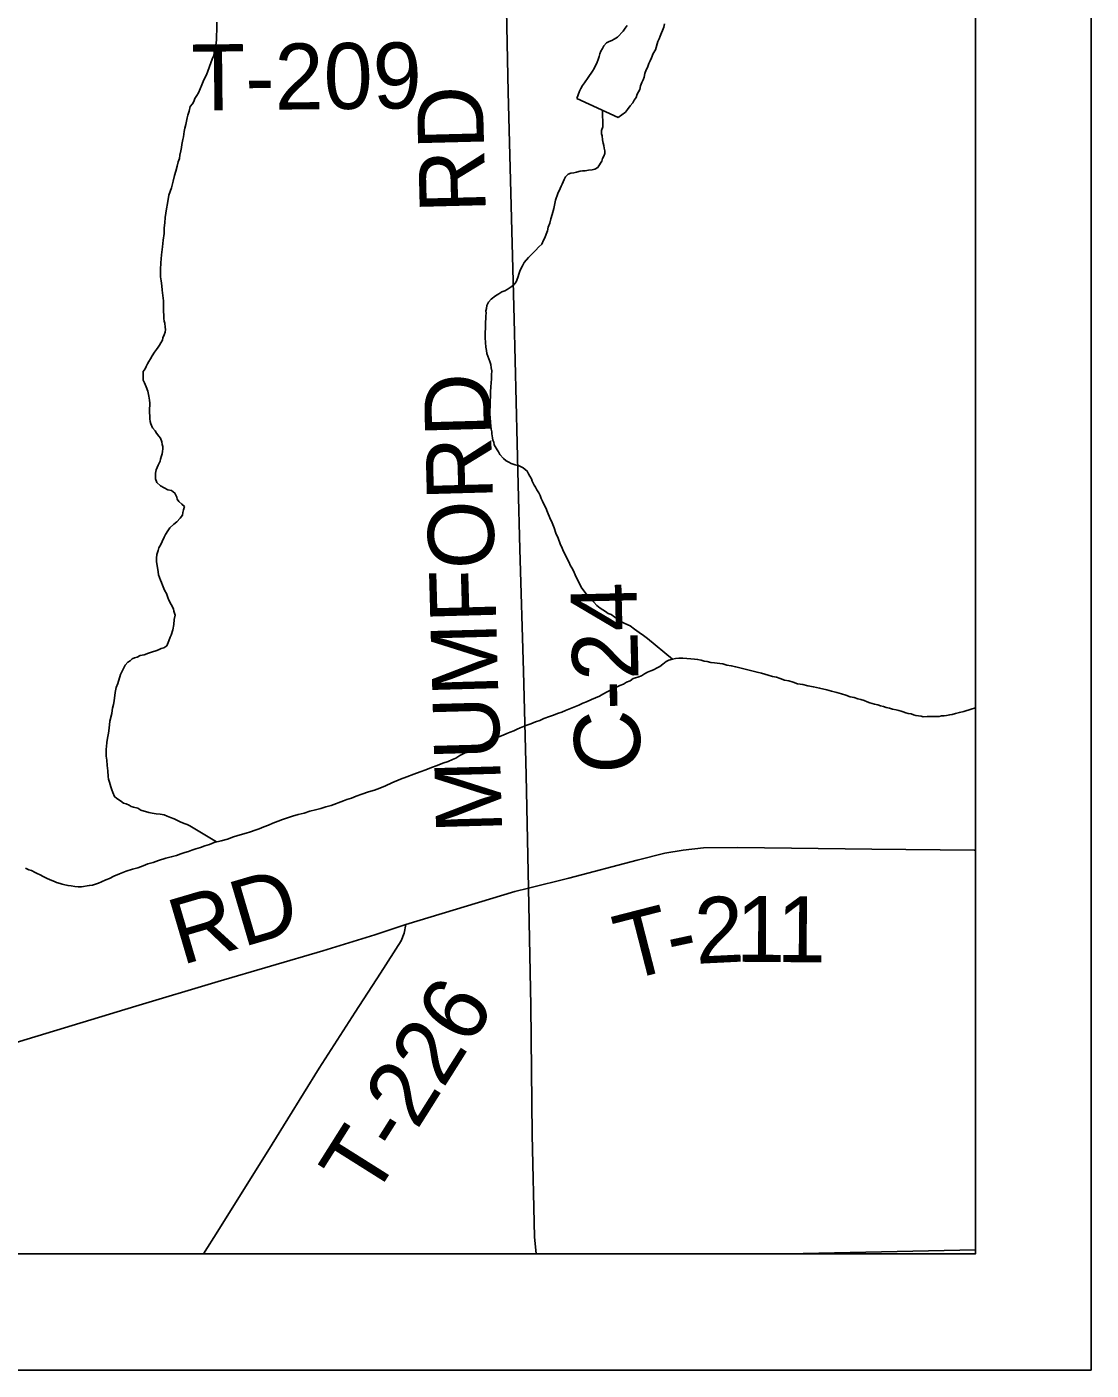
# Model space of a CAD drawing. Extents: x 10.6 to 44.6, y -2.6 to 23.4.
# Drawn here: x 19.186 to 20.103, y 15.426 to 16.584 of the extents above; entities that cross this region are included whole.
import ezdxf

# ---------------------------------------------------------------- set-up
doc = ezdxf.new("R2010")
doc.units = 0
for name, color, linetype in [('GM_X_Adjacent_County', 7, 'Continuous'), ('GM_X_County', 7, 'Continuous'), ('GM_X_County_Road', 7, 'Continuous'), ('GM_X_County_Road_Text', 7, 'Continuous'), ('GM_X_Minor_Lake', 7, 'Continuous'), ('GM_X_Minor_River', 7, 'Continuous'), ('GM_X_Township', 7, 'Continuous'), ('GM_X_Township_Road', 7, 'Continuous'), ('GM_X_Township_Road_Text', 7, 'Continuous'), ('SH_Data', 7, 'Continuous')]:
    doc.layers.add(name, color=color, linetype=linetype)

msp = doc.modelspace()

# ---------------------------------------------------------------- linework, layer by layer
at = {"layer": 'GM_X_Adjacent_County'}
msp.add_line((20.0033, 15.5302), (19.8413, 15.5267), dxfattribs=at)
msp.add_lwpolyline([(19.8413, 15.5267), (20.0033, 15.5267), (20.0033, 15.5302)], dxfattribs=at)
at = {"layer": 'GM_X_County'}
msp.add_line((19.8413, 15.5267), (20.0033, 15.5302), dxfattribs=at)
msp.add_lwpolyline([(20.0033, 15.5302), (20.0033, 22.3267), (13.2033, 22.3267), (13.2033, 15.5267), (19.8413, 15.5267)], dxfattribs=at)
at = {"layer": 'GM_X_County_Road'}
msp.add_lwpolyline([(19.6248, 15.5267), (19.6234, 15.5414), (19.6215, 15.6293), (19.6203, 15.7403), (19.6182, 15.8416), (19.6161, 15.9391), (19.614, 16.0288), (19.6109, 16.1339), (19.6094, 16.1895), (19.6059, 16.3321), (19.6008, 16.5277), (19.5991, 16.6126), (19.5971, 16.7116), (19.5964, 16.7781), (19.5922, 17.0526), (19.589, 17.2507), (19.5866, 17.4368), (19.5856, 17.5019), (19.5848, 17.5467)], dxfattribs=at)
at = {"layer": 'GM_X_Minor_Lake'}
msp.add_line((19.6598, 16.522), (19.6956, 16.5058), dxfattribs=at)
for points in [[(19.6956, 16.5058), (19.7017, 16.5104), (19.7035, 16.5127), (19.7058, 16.5157), (19.7081, 16.5184), (19.7092, 16.5207), (19.7111, 16.523), (19.7118, 16.526), (19.7141, 16.5299), (19.7148, 16.5329), (19.7159, 16.536), (19.717, 16.5383), (19.7178, 16.5405), (19.7185, 16.5436), (19.7196, 16.5467), (19.7208, 16.5489), (19.7219, 16.5524), (19.723, 16.5547), (19.7241, 16.5573), (19.7256, 16.5608), (19.7275, 16.5642), (19.7297, 16.5711), (19.7308, 16.5734), (19.7316, 16.5757), (19.7349, 16.5837), (19.7353, 16.5864)], [(19.7031, 16.5851), (19.7016, 16.5828), (19.6997, 16.5801), (19.6948, 16.5751), (19.6921, 16.5732), (19.6899, 16.572), (19.6876, 16.5713), (19.6853, 16.5701), (19.6831, 16.5674), (19.6819, 16.5651), (19.6804, 16.5628), (19.6797, 16.5606), (19.679, 16.5583), (19.6782, 16.5556), (19.6775, 16.5533), (19.6748, 16.548), (19.6733, 16.5457), (19.6696, 16.5403), (19.6666, 16.5357), (19.6647, 16.5334), (19.6632, 16.5308), (19.6621, 16.5285), (19.6598, 16.522)]]:
    msp.add_lwpolyline(points, dxfattribs=at)
at = {"layer": 'GM_X_Minor_River'}
for points in [[(19.3166, 16.4677), (19.3177, 16.4704), (19.318, 16.4734), (19.3187, 16.4769), (19.3194, 16.4799), (19.3197, 16.4826), (19.3204, 16.4868), (19.3211, 16.4891), (19.3218, 16.4937), (19.3224, 16.4967), (19.3231, 16.4998), (19.3238, 16.5025), (19.3242, 16.5055), (19.3249, 16.5078), (19.3259, 16.5113), (19.327, 16.5151), (19.3288, 16.5174), (19.3299, 16.5194), (19.331, 16.5221), (19.3325, 16.5248), (19.3339, 16.5271), (19.3354, 16.5305), (19.3368, 16.534), (19.3386, 16.5382), (19.3408, 16.5425), (19.3458, 16.5559), (19.3473, 16.5593), (19.3479, 16.5639), (19.349, 16.5681), (19.3496, 16.5723), (19.3495, 16.5769), (19.3498, 16.5803), (19.3498, 16.5838), (19.3497, 16.588)], [(19.582, 16.3411), (19.5823, 16.3438), (19.5838, 16.3465), (19.586, 16.3492), (19.5897, 16.352), (19.5927, 16.3539), (19.5953, 16.3555), (19.598, 16.3563), (19.5999, 16.3575), (19.6032, 16.3599), (19.6058, 16.3618), (19.6077, 16.3642), (19.6091, 16.368), (19.6102, 16.3715), (19.6109, 16.3734), (19.6116, 16.3753), (19.6131, 16.378), (19.6145, 16.3807), (19.6183, 16.385), (19.6212, 16.3881), (19.6242, 16.3912), (19.6272, 16.3943), (19.6298, 16.3966), (19.6312, 16.4001), (19.6323, 16.402), (19.6334, 16.4051), (19.6345, 16.4082), (19.6351, 16.4112), (19.6366, 16.4147), (19.6376, 16.4185), (19.6387, 16.4223), (19.6401, 16.4273), (19.6415, 16.4346), (19.6436, 16.4403), (19.6454, 16.4446), (19.6465, 16.4465), (19.6472, 16.4484), (19.649, 16.4523), (19.6501, 16.4546), (19.6524, 16.4569), (19.6546, 16.4577), (19.6573, 16.4582), (19.6595, 16.4586), (19.6626, 16.4594), (19.6648, 16.4599), (19.6671, 16.4599), (19.6698, 16.4603), (19.6732, 16.4608), (19.6755, 16.4612), (19.6781, 16.4628), (19.6803, 16.4663), (19.6814, 16.4682), (19.6821, 16.4705), (19.6832, 16.4724), (19.6839, 16.4748), (19.6839, 16.477), (19.6834, 16.4793), (19.683, 16.4816), (19.6826, 16.4835), (19.6821, 16.4865), (19.6817, 16.4899), (19.6812, 16.4918), (19.6812, 16.4945), (19.6822, 16.4976), (19.682, 16.512)], [(19.3057, 16.1465), (19.3076, 16.1496), (19.3094, 16.1523), (19.3127, 16.1554), (19.3154, 16.1574), (19.3183, 16.1605), (19.3202, 16.1632), (19.3205, 16.1655), (19.3212, 16.1678), (19.3219, 16.1705), (19.3196, 16.1727), (19.3172, 16.175), (19.3157, 16.1768), (19.3153, 16.1787), (19.3137, 16.1821), (19.3109, 16.1843), (19.3075, 16.185), (19.3013, 16.1883), (19.2982, 16.1913), (19.297, 16.1943), (19.297, 16.1973), (19.2969, 16.1992), (19.2976, 16.2023), (19.2994, 16.2062), (19.3009, 16.2096), (19.3012, 16.2115), (19.3023, 16.2142), (19.3026, 16.2161), (19.3029, 16.218), (19.3033, 16.2203), (19.3032, 16.2222), (19.3028, 16.2241), (19.3024, 16.2264), (19.3012, 16.2294), (19.3, 16.2313), (19.298, 16.2339), (19.2968, 16.2358), (19.2945, 16.2384), (19.2929, 16.2418), (19.2925, 16.2437), (19.292, 16.246), (19.292, 16.2486), (19.2919, 16.2513), (19.2918, 16.2547), (19.2922, 16.2578), (19.2921, 16.2597), (19.2917, 16.2623), (19.2912, 16.2657), (19.2904, 16.2699), (19.2891, 16.2737), (19.2875, 16.2771), (19.2863, 16.2793), (19.2865, 16.2869), (19.288, 16.2893), (19.2891, 16.2912), (19.2902, 16.2935), (19.2913, 16.2954), (19.2928, 16.2977), (19.2942, 16.3004), (19.2961, 16.3035), (19.2979, 16.3059), (19.2994, 16.3078), (19.3005, 16.3097), (19.3016, 16.3116), (19.303, 16.314), (19.3034, 16.3159), (19.3045, 16.3186), (19.3052, 16.3209), (19.3055, 16.3232), (19.3054, 16.3251), (19.305, 16.3285), (19.3046, 16.3304), (19.3041, 16.3326), (19.3041, 16.3357), (19.304, 16.3383), (19.3039, 16.3437), (19.3038, 16.3479), (19.3028, 16.357), (19.3024, 16.3608), (19.3019, 16.3649), (19.3014, 16.3684), (19.3014, 16.3714), (19.3013, 16.3748), (19.3015, 16.3805), (19.3021, 16.3874), (19.3031, 16.3943), (19.3037, 16.4), (19.3044, 16.4057), (19.3046, 16.4107), (19.3049, 16.4149), (19.3052, 16.4195), (19.3059, 16.4233), (19.3065, 16.4271), (19.3072, 16.4317), (19.3086, 16.4389), (19.3107, 16.4451), (19.3121, 16.4508), (19.3135, 16.4558), (19.3145, 16.4596), (19.3156, 16.4639), (19.3166, 16.4677)], [(19.7422, 16.039), (19.7208, 16.0568), (19.7173, 16.0594), (19.7135, 16.062), (19.7096, 16.065), (19.7057, 16.0679), (19.7011, 16.0697), (19.6984, 16.0712), (19.6957, 16.073), (19.6926, 16.0752), (19.6895, 16.0774), (19.6869, 16.0785), (19.6845, 16.08), (19.6822, 16.0815), (19.6799, 16.0829), (19.6772, 16.0852), (19.6745, 16.0882), (19.671, 16.0915), (19.6686, 16.0945), (19.6663, 16.0975), (19.6643, 16.1001), (19.6595, 16.1091), (19.6583, 16.1118), (19.6571, 16.1152), (19.6555, 16.1178), (19.654, 16.12), (19.6532, 16.1223), (19.652, 16.1242), (19.65, 16.1287), (19.6484, 16.1317), (19.6472, 16.1347), (19.6456, 16.1385), (19.6439, 16.1434), (19.6419, 16.1476), (19.6403, 16.1521), (19.6387, 16.1566), (19.6367, 16.1608), (19.6347, 16.1657), (19.6331, 16.1695), (19.6315, 16.1725), (19.6303, 16.1751), (19.6291, 16.1774), (19.6283, 16.18), (19.6271, 16.1823), (19.6255, 16.1849), (19.6243, 16.1871), (19.6231, 16.189), (19.6215, 16.1924), (19.6207, 16.1943), (19.6195, 16.1966), (19.6183, 16.1988), (19.6171, 16.2011), (19.6136, 16.204), (19.6102, 16.2055), (19.6067, 16.2066), (19.6033, 16.2076), (19.6014, 16.2087), (19.599, 16.2098), (19.5967, 16.212), (19.5936, 16.2154), (19.5924, 16.2176), (19.5912, 16.2195), (19.5888, 16.2237), (19.5884, 16.2259), (19.5876, 16.2278), (19.5872, 16.2297), (19.5867, 16.2331), (19.5867, 16.235), (19.5862, 16.2373), (19.5858, 16.24), (19.5854, 16.243), (19.5853, 16.2476), (19.5848, 16.2517), (19.5851, 16.2563), (19.5853, 16.2613), (19.5856, 16.2655), (19.5855, 16.2696), (19.5858, 16.2735), (19.5861, 16.2773), (19.5864, 16.2803), (19.5863, 16.2841), (19.5866, 16.2876), (19.5862, 16.2902), (19.5857, 16.2929), (19.5849, 16.2955), (19.5841, 16.2978), (19.5833, 16.3001), (19.5825, 16.3023), (19.582, 16.305), (19.5816, 16.308), (19.5811, 16.3118), (19.581, 16.316), (19.5809, 16.3202), (19.5812, 16.3244), (19.5812, 16.327), (19.5811, 16.3297), (19.5814, 16.3324), (19.5814, 16.335), (19.5817, 16.3373), (19.5816, 16.3392), (19.582, 16.3411)], [(19.3496, 15.8817), (19.3267, 15.8954), (19.3244, 15.8965), (19.3217, 15.8975), (19.3182, 15.899), (19.3132, 15.9015), (19.3098, 15.9026), (19.3071, 15.9037), (19.3044, 15.9048), (19.301, 15.9055), (19.2975, 15.9058), (19.2941, 15.9064), (19.2914, 15.9068), (19.2845, 15.9089), (19.2818, 15.9107), (19.278, 15.9114), (19.2761, 15.9121), (19.2742, 15.9132), (19.2718, 15.9143), (19.2695, 15.915), (19.2668, 15.9169), (19.2638, 15.9191), (19.2618, 15.9206), (19.2602, 15.9243), (19.2594, 15.9266), (19.2586, 15.9289), (19.2573, 15.933), (19.2565, 15.9357), (19.2561, 15.9379), (19.256, 15.9429), (19.2555, 15.9475), (19.255, 15.952), (19.2546, 15.9554), (19.2545, 15.9589), (19.2544, 15.9615), (19.2547, 15.9638), (19.255, 15.9672), (19.2557, 15.9711), (19.2564, 15.9753), (19.257, 15.9795), (19.2577, 15.9856), (19.2594, 15.9921), (19.2597, 15.9948), (19.2601, 15.9967), (19.2608, 16.0001), (19.2615, 16.0032), (19.2618, 16.0058), (19.2621, 16.0077), (19.2624, 16.0104), (19.2631, 16.0146), (19.2645, 16.0181), (19.267, 16.0258), (19.2681, 16.0281), (19.2692, 16.0304), (19.271, 16.0338), (19.2732, 16.0365), (19.2751, 16.0377), (19.277, 16.0393), (19.2789, 16.0401), (19.2811, 16.0409), (19.2838, 16.0421), (19.2872, 16.0429), (19.2909, 16.0442), (19.2943, 16.0454), (19.2974, 16.0462), (19.2996, 16.047), (19.3019, 16.0482), (19.3042, 16.0487), (19.3068, 16.0506), (19.3086, 16.0548), (19.3096, 16.0579), (19.3104, 16.0598), (19.3118, 16.0644), (19.3128, 16.069), (19.3131, 16.0732), (19.3138, 16.077), (19.3129, 16.0805), (19.3125, 16.0823), (19.3105, 16.0861), (19.3085, 16.0899), (19.3077, 16.0921), (19.3065, 16.0955), (19.3049, 16.0978), (19.3041, 16.1), (19.3029, 16.1027), (19.3021, 16.105), (19.3013, 16.1072), (19.3005, 16.1095), (19.2997, 16.1118), (19.2992, 16.1144), (19.2979, 16.1231), (19.2978, 16.1262), (19.2981, 16.1292), (19.2992, 16.1327), (19.2999, 16.135), (19.3017, 16.1377), (19.3028, 16.1404), (19.3046, 16.1442), (19.3057, 16.1465)], [(19.7057, 16.0203), (19.7083, 16.0223), (19.7125, 16.0235), (19.7155, 16.0247), (19.7181, 16.0263), (19.7207, 16.0279), (19.7237, 16.0291), (19.726, 16.0299), (19.729, 16.0315), (19.7313, 16.0327), (19.7339, 16.0347), (19.7369, 16.037), (19.7391, 16.0382), (19.7422, 16.039), (19.7448, 16.0395), (19.7478, 16.0399), (19.7513, 16.04), (19.7547, 16.0397), (19.7581, 16.0394), (19.7612, 16.0391), (19.7638, 16.0388), (19.7669, 16.0381), (19.7696, 16.0374), (19.7722, 16.037), (19.7753, 16.0363), (19.7784, 16.036), (19.7829, 16.0354), (19.7856, 16.0351), (19.789, 16.034), (19.7929, 16.0333), (19.7967, 16.0323), (19.8013, 16.0312), (19.8151, 16.0277), (19.8189, 16.027), (19.8219, 16.026), (19.8246, 16.0253), (19.8284, 16.0242), (19.8319, 16.0235), (19.835, 16.0225), (19.8388, 16.021), (19.8426, 16.0203), (19.8461, 16.0193), (19.8499, 16.0178), (19.8545, 16.0172), (19.8587, 16.0161), (19.8636, 16.0151), (19.869, 16.0141), (19.8751, 16.0127), (19.8793, 16.0116), (19.8839, 16.0102), (19.8877, 16.0092), (19.8916, 16.0081), (19.8954, 16.0067), (19.8988, 16.006), (19.9019, 16.0049), (19.9046, 16.0042), (19.9073, 16.0035), (19.91, 16.0024), (19.9123, 16.0013), (19.9161, 16.0003), (19.9192, 15.9996), (19.9215, 15.9989), (19.9241, 15.9982), (19.9264, 15.9975), (19.9291, 15.9968), (19.9318, 15.9961), (19.9348, 15.9954), (19.9371, 15.9947), (19.9391, 15.9943), (19.941, 15.9936), (19.9433, 15.9929), (19.9452, 15.9922), (19.9479, 15.9919), (19.9498, 15.9911), (19.9517, 15.9904), (19.954, 15.9901), (19.9563, 15.9898), (19.9582, 15.9894), (19.9616, 15.9895), (19.965, 15.9896), (19.9719, 15.9897), (19.9738, 15.9902), (19.976, 15.9902), (19.9783, 15.9906), (19.981, 15.9911), (19.9832, 15.9915), (19.9859, 15.9923), (19.9893, 15.9932), (19.9931, 15.994), (19.9995, 15.9961), (20.0033, 15.997)], [(19.2905, 15.8626), (19.2951, 15.8638), (19.2996, 15.8655), (19.306, 15.8675), (19.3105, 15.8687), (19.3151, 15.87), (19.3189, 15.8712), (19.3222, 15.8724), (19.3253, 15.8733), (19.3283, 15.8745), (19.3317, 15.8757), (19.3358, 15.8769), (19.3396, 15.8781), (19.3434, 15.8794), (19.3475, 15.881), (19.3536, 15.8826), (19.3589, 15.8839), (19.3642, 15.8859), (19.3698, 15.8876), (19.3751, 15.8892), (19.3789, 15.8904), (19.3827, 15.8917), (19.3864, 15.8929), (19.3902, 15.8945), (19.3944, 15.8961), (19.3981, 15.8977), (19.4026, 15.8994), (19.4064, 15.901), (19.4106, 15.9022), (19.4151, 15.9038), (19.42, 15.9051), (19.4249, 15.9063), (19.4298, 15.908), (19.4348, 15.9092), (19.4393, 15.9104), (19.4438, 15.9117), (19.4484, 15.9129), (19.4589, 15.917), (19.4619, 15.9182), (19.4657, 15.9194), (19.4699, 15.921), (19.4748, 15.9227), (19.4804, 15.9247), (19.4857, 15.9263), (19.4902, 15.928), (19.4951, 15.93), (19.5004, 15.9324), (19.5079, 15.9356), (19.5136, 15.9376), (19.5196, 15.94), (19.5249, 15.9421), (19.5298, 15.9437), (19.5347, 15.9457), (19.5396, 15.9473), (19.5445, 15.9493), (19.549, 15.951), (19.5528, 15.9526), (19.5558, 15.9538), (19.5592, 15.9561), (19.5648, 15.9589), (19.569, 15.9609), (19.5731, 15.9625), (19.575, 15.9634), (19.578, 15.9653), (19.5803, 15.9665), (19.5829, 15.9677), (19.5863, 15.9697), (19.5897, 15.9709), (19.5927, 15.9721), (19.5964, 15.9737), (19.5995, 15.9749), (19.6025, 15.9761), (19.6055, 15.9774), (19.6085, 15.9786), (19.6111, 15.9798), (19.6138, 15.981), (19.6168, 15.9822), (19.6202, 15.9834), (19.6243, 15.985), (19.6281, 15.9862), (19.6315, 15.9878), (19.6364, 15.9895), (19.6398, 15.9907), (19.6432, 15.9923), (19.647, 15.9935), (19.65, 15.9947), (19.6586, 15.9983), (19.6617, 15.9995), (19.665, 16.0011), (19.6681, 16.0024), (19.6726, 16.0044), (19.676, 16.0056), (19.6794, 16.0072), (19.6824, 16.0088), (19.6861, 16.0108), (19.6895, 16.0127), (19.6936, 16.0147), (19.697, 16.0163), (19.7, 16.0175), (19.7027, 16.0191), (19.7057, 16.0203)], [(19.1849, 15.8591), (19.1879, 15.8576), (19.1902, 15.8569), (19.1933, 15.8551), (19.1952, 15.8544), (19.1976, 15.8533), (19.2002, 15.8518), (19.2037, 15.85), (19.2056, 15.8493), (19.2076, 15.8482), (19.2099, 15.8475), (19.2118, 15.8467), (19.2148, 15.8457), (19.2167, 15.8453), (19.219, 15.8446), (19.2217, 15.8439), (19.2244, 15.8436), (19.2274, 15.8433), (19.2305, 15.843), (19.2332, 15.843), (19.24, 15.8439), (19.2426, 15.8444), (19.2453, 15.8452), (19.2479, 15.846), (19.2506, 15.8472), (19.2543, 15.8488), (19.2573, 15.85), (19.2611, 15.852), (19.266, 15.854), (19.2716, 15.8565), (19.2773, 15.8581), (19.2818, 15.8593), (19.2864, 15.861), (19.2905, 15.8626)]]:
    msp.add_lwpolyline(points, dxfattribs=at)
at = {"layer": 'GM_X_Township'}
for p, q in [((20.0033, 15.5302), (20.0033, 20.9573)), ((15.2903, 15.5267), (19.8413, 15.5267)), ((19.8413, 15.5267), (20.0033, 15.5302))]:
    msp.add_line(p, q, dxfattribs=at)
at = {"layer": 'GM_X_Township_Road'}
for points in [[(19.6182, 15.8416), (19.6531, 15.8504), (19.7119, 15.8658), (19.7357, 15.8718), (19.7515, 15.8746), (19.7689, 15.8765), (19.7985, 15.8767), (19.914, 15.8753), (20.0022, 15.8744), (20.0033, 15.8744)], [(19.1639, 15.7048), (19.2802, 15.7401), (19.3511, 15.7613), (19.441, 15.7878), (19.486, 15.8015), (19.5125, 15.8103), (19.6065, 15.839), (19.6182, 15.8416)], [(19.5125, 15.8103), (19.5113, 15.803), (19.5086, 15.7964), (19.4907, 15.7684), (19.4691, 15.7349), (19.438, 15.6866), (19.3974, 15.6211), (19.3506, 15.5463), (19.3382, 15.5267)]]:
    msp.add_lwpolyline(points, dxfattribs=at)
at = {"layer": 'SH_Data'}
for p in [(20.1028, 22.4265), (13.1028, 15.4265)]:
    msp.add_line(p, (20.1028, 15.4265), dxfattribs=at)

# ---------------------------------------------------------------- texts
at = {"layer": 'GM_X_County_Road_Text'}
for s, rotation, p in [('RD', 91.4825, (19.5815, 16.424)), ('MUMFORD', 91.5871, (19.5956, 15.8897)), ('C-24', 91.3645, (19.715, 15.9411))]:
    msp.add_text(s, height=0.05682, rotation=rotation, dxfattribs=at).set_placement(p)
at = {"layer": 'GM_X_Township_Road_Text'}
for s, height, rotation, p in [('T-209', 0.05682, 0.5614, (19.3281, 16.5118)), ('RD', 0.05682, 16.4164, (19.3193, 15.7752)), ('2', 0.0568, 2.8424, (19.7627, 15.7765)), ('1', 0.0568, 359.6826, (19.7968, 15.7783)), ('1', 0.0568, 359.3963, (19.8318, 15.7781)), ('T', 0.0568, 14.3699, (19.7017, 15.7615)), ('-', 0.0568, 12.1275, (19.7423, 15.772)), ('T-226', 0.05682, 57.7874, (19.4839, 15.572))]:
    msp.add_text(s, height=height, rotation=rotation, dxfattribs=at).set_placement(p)

doc.saveas('drawing.dxf')
